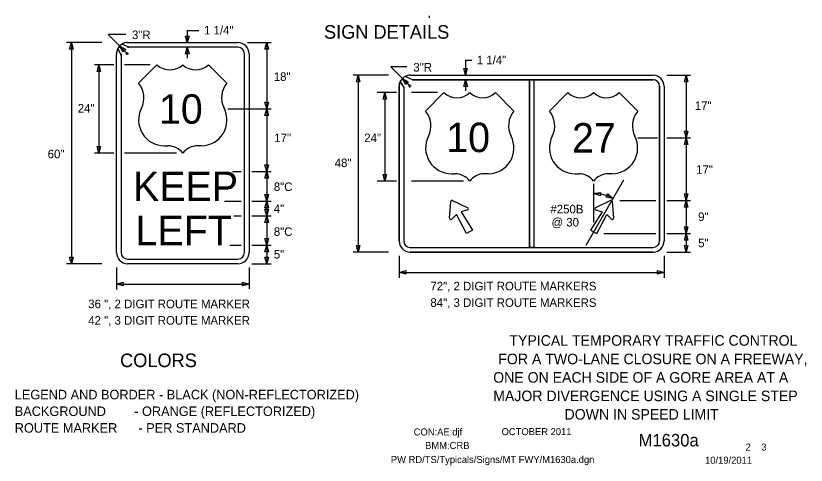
# Model space of a CAD drawing. Extents: x 16512 to 19512, y 5761 to 6974.
# Drawn here: x 17768 to 18466, y 5932 to 6328 of the extents above; entities that cross this region are included whole.
import ezdxf

# ---------------------------------------------------------------- set-up
doc = ezdxf.new("R2010")
doc.units = 0
for name, color, linetype in [('ALI_LEGAL_EX', 7, 'Continuous'), ('BORDER', 7, 'Continuous'), ('BORDER_SIGNAL_WO', 7, 'Continuous'), ('TRAFFIC_SIGNS_PR', 7, 'Continuous'), ('TYPICAL_EX', 7, 'Continuous'), ('TYPICAL_TEXT_DIMEN_PR', 7, 'Continuous')]:
    doc.layers.add(name, color=color, linetype=linetype)

msp = doc.modelspace()

# ---------------------------------------------------------------- linework, layer by layer
at = {"layer": 'ALI_LEGAL_EX'}
msp.add_lwpolyline([(18133.42, 6328.26), (18133.42, 6326.51)], dxfattribs=at)
at = {"layer": 'TRAFFIC_SIGNS_PR'}
for p, q in [((17859.5, 6300.96), (17858.5, 6299.45)), ((17868.29, 6300.52), (17862.19, 6303.27)), ((17867.09, 6304.58), (17964.59, 6304.58)), ((17857.34, 6119.33), (17857.34, 6294.83)), ((17858.53, 6299.39), (17861.4, 6293.35)), ((17861.4, 6294.83), (17861.4, 6119.33)), ((17964.59, 6300.52), (17867.09, 6300.52)), ((17970.27, 6119.33), (17970.27, 6294.83)), ((17974.34, 6294.83), (17974.34, 6119.33)), ((18118.56, 6271.83), (18112.33, 6274.85)), ((18116.61, 6275.88), (18331.11, 6275.88)), ((18116.61, 6275.88), (18331.11, 6275.88)), ((18106.86, 6266.13), (18106.86, 6129.63)), ((18106.86, 6129.63), (18106.86, 6266.13)), ((18107.78, 6270.14), (18110.91, 6265.1)), ((18118.55, 6271.82), (18221.83, 6271.82)), ((18331.11, 6271.82), (18118.55, 6271.82)), ((18221.83, 6271.82), (18221.83, 6123.95)), ((18225.89, 6271.82), (18225.89, 6123.95)), ((18225.89, 6271.82), (18331.11, 6271.82)), ((18336.8, 6266.13), (18336.8, 6220.38)), ((18336.8, 6129.63), (18336.8, 6266.13)), ((18340.86, 6266.13), (18340.86, 6129.63)), ((18340.86, 6266.13), (18340.86, 6129.63)), ((18110.92, 6265.08), (18110.92, 6129.63)), ((18110.92, 6265.08), (18110.92, 6129.63)), ((18336.8, 6220.38), (18336.8, 6129.63)), ((18151.46, 6149.74), (18152.61, 6164.46)), ((18154.12, 6165.33), (18167.44, 6158.97)), ((18293.59, 6165.33), (18280.28, 6158.97)), ((18296.26, 6149.74), (18295.1, 6164.46)), ((18116.61, 6123.95), (18331.11, 6123.95)), ((18116.61, 6119.88), (18331.11, 6119.88)), ((18331.11, 6119.88), (18116.61, 6119.88)), ((17867.09, 6113.64), (17964.59, 6113.64)), ((17964.59, 6109.58), (17867.09, 6109.58))]:
    msp.add_line(p, q, dxfattribs=at)
for points in [[(18118.55, 6271.82), (18118.53, 6271.83)], [(18110.91, 6265.1), (18110.92, 6265.08)], [(18167.28, 6157), (18161.55, 6155.42), (18171.77, 6139.25), (18166.37, 6136.13), (18157.48, 6153.07), (18153.25, 6148.9)], [(18280.44, 6157), (18286.16, 6155.42), (18275.95, 6139.25), (18281.34, 6136.13), (18290.24, 6153.07), (18294.46, 6148.9)]]:
    msp.add_lwpolyline(points, dxfattribs=at)
msp.add_lwpolyline([(18221.83, 6271.82), (18225.89, 6271.82), (18225.89, 6123.95), (18221.83, 6123.95)], close=True, dxfattribs=at)
for centre, radius, start, end in [((17867.09, 6294.83), 9.75, 90, 180), ((17866.5, 6297.01), 7.6, 85.58319, 124.53531), ((17964.59, 6294.83), 9.75, 0, 90), ((17864.37, 6295.43), 7.06, 145.86811, 184.82317), ((17855.94, 6294.09), 5.51, 352.24294, 7.75653), ((17867.69, 6304.95), 4.47, 262.2432, 277.7568), ((17964.59, 6294.83), 5.69, 0, 90), ((18116.61, 6266.13), 9.75, 90, 180), ((18116.61, 6266.13), 9.75, 90, 180), ((18115.93, 6269.32), 6.6, 84.11162, 123.06374), ((18331.11, 6266.13), 9.75, 0, 90), ((18331.11, 6266.13), 9.75, 0, 90), ((18112.99, 6266.84), 6.17, 147.60925, 186.56283), ((18117.55, 6279), 7.24, 277.81035, 278.05403), ((18331.11, 6266.13), 5.69, 0, 89.99421), ((18331.11, 6266.13), 5.69, 0, 90), ((18153.67, 6164.37), 1.06, 64.48226, 175.51774), ((18294.05, 6164.37), 1.06, 4.48226, 115.51774), ((18166.98, 6158.02), 1.06, 285.9885, 64.48226), ((18280.73, 6158.02), 1.06, 115.51774, 254.0115), ((18152.52, 6149.66), 1.06, 175.51775, 314.01151), ((18295.2, 6149.66), 1.06, 225.98849, 4.48225), ((18116.61, 6129.63), 9.75, 180, 270), ((18116.61, 6129.63), 9.75, 180, 270), ((18116.61, 6129.63), 5.69, 180, 270), ((18116.61, 6129.63), 5.69, 180, 270), ((18331.11, 6129.63), 9.75, 270, 0), ((18331.11, 6129.63), 5.69, 270, 0), ((18331.11, 6129.63), 9.75, 270, 0), ((18331.11, 6129.63), 5.69, 270, 0), ((17867.09, 6119.33), 9.75, 180, 270), ((17867.09, 6119.33), 5.69, 180, 270), ((17964.59, 6119.33), 5.69, 270, 0), ((17964.59, 6119.33), 9.75, 270, 0)]:
    msp.add_arc(centre, radius, start, end, dxfattribs=at)
at = {"layer": 'TYPICAL_EX'}
for p, q in [((17876.84, 6268.84), (17893.09, 6285.09)), ((17954.84, 6268.84), (17938.59, 6285.09)), ((18130.22, 6244.22), (18146.47, 6260.47)), ((18208.22, 6244.22), (18191.97, 6260.47)), ((18239.5, 6244.22), (18255.75, 6260.47)), ((18317.5, 6244.22), (18301.25, 6260.47)), ((17899.56, 6213.54), (17902.81, 6213.54)), ((17932.11, 6213.54), (17928.86, 6213.54)), ((18152.95, 6188.93), (18156.2, 6188.93)), ((18185.49, 6188.93), (18182.24, 6188.93)), ((18262.22, 6188.93), (18265.47, 6188.93)), ((18294.77, 6188.93), (18291.52, 6188.93))]:
    msp.add_line(p, q, dxfattribs=at)
for centre, radius, start, end in [((17904.46, 6296.92), 16.42, 226.14041, 313.85958), ((17927.21, 6296.92), 16.42, 226.14042, 313.85959), ((17861.44, 6255.82), 20.16, 333.09768, 40.19361), ((17970.24, 6255.82), 20.16, 139.80639, 206.90233), ((18157.85, 6272.31), 16.42, 226.14041, 313.85958), ((18180.59, 6272.31), 16.42, 226.14042, 313.85959), ((18267.12, 6272.31), 16.42, 226.14041, 313.85958), ((18289.87, 6272.31), 16.42, 226.14042, 313.85959), ((17899.6, 6236.27), 22.73, 152.6698, 269.90132), ((17932.07, 6236.27), 22.73, 270.09868, 27.3302), ((18114.82, 6231.21), 20.16, 333.09768, 40.19361), ((18223.62, 6231.21), 20.16, 139.80639, 206.90233), ((18224.1, 6231.21), 20.16, 333.09768, 40.19361), ((18332.9, 6231.21), 20.16, 139.80639, 206.90233), ((18152.99, 6211.66), 22.73, 152.6698, 269.90132), ((18185.45, 6211.66), 22.73, 270.09868, 27.3302), ((18262.27, 6211.66), 22.73, 152.6698, 269.90132), ((18294.73, 6211.66), 22.73, 270.09868, 27.3302), ((17902.85, 6197.26), 16.28, 37.1038, 90.13853), ((17928.82, 6197.26), 16.28, 89.86147, 142.8962), ((18156.24, 6172.65), 16.28, 37.1038, 90.13853), ((18182.2, 6172.65), 16.28, 89.86147, 142.8962), ((18265.52, 6172.65), 16.28, 37.1038, 90.13853), ((18291.48, 6172.65), 16.28, 89.86147, 142.8962)]:
    msp.add_arc(centre, radius, start, end, dxfattribs=at)
at = {"layer": 'TYPICAL_TEXT_DIMEN_PR'}
for p, q in [((17919.81, 6315.34), (17919.81, 6304.58)), ((17919.81, 6315.34), (17929.91, 6315.34)), ((17865.71, 6311.86), (17850.05, 6311.86)), ((17850.05, 6311.86), (17860.29, 6301.63)), ((17919.81, 6304.58), (17918.24, 6310.44)), ((17918.24, 6310.44), (17919.81, 6310.44)), ((17919.81, 6310.44), (17921.38, 6310.44)), ((17921.38, 6310.44), (17919.81, 6304.58)), ((17844.51, 6304.58), (17813.21, 6304.58)), ((17815.98, 6298.72), (17817.55, 6304.58)), ((17817.55, 6304.58), (17817.55, 6109.58)), ((17817.55, 6304.58), (17819.12, 6298.72)), ((17860.29, 6301.63), (17866.85, 6295.07)), ((17863.32, 6296.37), (17860.29, 6301.63)), ((17860.29, 6301.63), (17865.54, 6298.6)), ((17972.88, 6304.58), (17993.84, 6304.58)), ((17988.37, 6298.72), (17989.94, 6304.58)), ((17989.94, 6304.58), (17989.94, 6246.08)), ((17989.94, 6304.58), (17991.51, 6298.72)), ((17817.55, 6298.72), (17815.98, 6298.72)), ((17819.12, 6298.72), (17817.55, 6298.72)), ((17864.43, 6297.49), (17863.32, 6296.37)), ((17865.54, 6298.6), (17864.43, 6297.49)), ((17865.64, 6295.07), (17868.05, 6295.07)), ((17866.85, 6293.86), (17866.85, 6296.28)), ((17918.28, 6294.66), (17919.86, 6300.52)), ((17919.86, 6294.66), (17918.28, 6294.66)), ((17919.86, 6300.52), (17919.86, 6290.77)), ((17919.86, 6300.52), (17921.43, 6294.66)), ((17921.43, 6294.66), (17919.86, 6294.66)), ((17989.94, 6298.72), (17988.37, 6298.72)), ((17991.51, 6298.72), (17989.94, 6298.72)), ((18165.47, 6289.03), (18165.47, 6275.88)), ((18165.47, 6289.03), (18170.99, 6289.03)), ((17854.96, 6285.08), (17837.84, 6285.08)), ((17840.16, 6279.22), (17841.73, 6285.08)), ((17841.73, 6285.08), (17841.73, 6207.08)), ((17841.73, 6285.08), (17843.3, 6279.22)), ((17887.2, 6285.08), (17864.33, 6285.08)), ((18113.75, 6283.17), (18099.57, 6283.17)), ((18099.57, 6283.17), (18109.72, 6273.02)), ((18165.47, 6275.88), (18163.89, 6281.74)), ((18163.89, 6281.74), (18165.47, 6281.74)), ((18165.47, 6281.74), (18167.04, 6281.74)), ((18167.04, 6281.74), (18165.47, 6275.88)), ((17841.73, 6279.22), (17840.16, 6279.22)), ((17843.3, 6279.22), (17841.73, 6279.22)), ((18097.62, 6275.88), (18066.33, 6275.88)), ((18069.1, 6270.02), (18070.67, 6275.88)), ((18070.67, 6275.88), (18070.67, 6119.88)), ((18070.67, 6275.88), (18072.24, 6270.02)), ((18109.72, 6273.02), (18116.37, 6266.37)), ((18112.76, 6267.76), (18109.72, 6273.02)), ((18109.72, 6273.02), (18114.98, 6269.99)), ((18343.23, 6275.88), (18364.19, 6275.88)), ((18358.72, 6270.02), (18360.29, 6275.88)), ((18360.29, 6275.88), (18360.29, 6220.63)), ((18360.29, 6275.88), (18361.86, 6270.02)), ((18070.67, 6270.02), (18069.1, 6270.02)), ((18072.24, 6270.02), (18070.67, 6270.02)), ((18113.87, 6268.88), (18112.76, 6267.76)), ((18114.98, 6269.99), (18113.87, 6268.88)), ((18115.16, 6266.37), (18117.58, 6266.37)), ((18116.37, 6265.16), (18116.37, 6267.58)), ((18163.94, 6265.96), (18165.51, 6271.82)), ((18163.94, 6265.96), (18165.51, 6271.82)), ((18165.51, 6271.82), (18165.51, 6262.07)), ((18165.51, 6271.82), (18167.08, 6265.96)), ((18165.51, 6271.82), (18167.08, 6265.96)), ((18360.29, 6270.02), (18358.72, 6270.02)), ((18361.86, 6270.02), (18360.29, 6270.02)), ((18104.49, 6260.47), (18087.36, 6260.47)), ((18092.65, 6254.61), (18094.23, 6260.47)), ((18094.23, 6260.47), (18094.23, 6182.47)), ((18094.23, 6260.47), (18095.8, 6254.61)), ((18140.59, 6260.47), (18117.71, 6260.47)), ((18165.51, 6265.96), (18163.94, 6265.96)), ((18165.51, 6265.96), (18163.94, 6265.96)), ((18167.08, 6265.96), (18165.51, 6265.96)), ((18167.08, 6265.96), (18165.51, 6265.96)), ((18094.23, 6254.61), (18092.65, 6254.61)), ((18095.8, 6254.61), (18094.23, 6254.61)), ((17955.73, 6246.08), (17993.84, 6246.08)), ((17989.94, 6246.08), (17988.37, 6251.94)), ((17988.37, 6251.94), (17989.94, 6251.94)), ((17988.37, 6240.22), (17989.94, 6246.08)), ((17989.94, 6251.94), (17991.51, 6251.94)), ((17991.51, 6251.94), (17989.94, 6246.08)), ((17989.94, 6246.08), (17989.94, 6190.83)), ((17989.94, 6246.08), (17991.51, 6240.22)), ((17989.94, 6240.22), (17988.37, 6240.22)), ((17991.51, 6240.22), (17989.94, 6240.22)), ((18360.29, 6220.63), (18358.72, 6226.49)), ((18358.72, 6226.49), (18360.29, 6226.49)), ((18360.29, 6226.49), (18361.86, 6226.49)), ((18361.86, 6226.49), (18360.29, 6220.63)), ((18317.67, 6220.63), (18334.82, 6220.63)), ((18343.23, 6220.63), (18364.19, 6220.63)), ((18358.72, 6214.77), (18360.29, 6220.63)), ((18360.29, 6220.63), (18360.29, 6165.38)), ((18360.29, 6220.63), (18361.86, 6214.77)), ((17841.73, 6207.08), (17840.16, 6212.94)), ((17840.16, 6212.94), (17841.73, 6212.94)), ((17841.73, 6212.94), (17843.3, 6212.94)), ((17843.3, 6212.94), (17841.73, 6207.08)), ((18360.29, 6214.77), (18358.72, 6214.77)), ((18361.86, 6214.77), (18360.29, 6214.77)), ((17854.96, 6207.08), (17837.84, 6207.08)), ((17910.33, 6207.08), (17864.33, 6207.08)), ((17989.94, 6190.83), (17988.37, 6196.69)), ((17988.37, 6196.69), (17989.94, 6196.69)), ((17989.94, 6196.69), (17991.51, 6196.69)), ((17991.51, 6196.69), (17989.94, 6190.83)), ((17959.66, 6190.83), (17967.35, 6190.83)), ((17976.71, 6190.83), (17993.84, 6190.83)), ((17988.37, 6184.97), (17989.94, 6190.83)), ((17989.94, 6190.83), (17989.94, 6164.83)), ((17989.94, 6190.83), (17991.51, 6184.97)), ((17989.94, 6184.97), (17988.37, 6184.97)), ((17991.51, 6184.97), (17989.94, 6184.97)), ((18104.49, 6182.47), (18087.36, 6182.47)), ((18094.23, 6182.47), (18092.65, 6188.33)), ((18092.65, 6188.33), (18094.23, 6188.33)), ((18094.23, 6188.33), (18095.8, 6188.33)), ((18095.8, 6188.33), (18094.23, 6182.47)), ((18163.71, 6182.47), (18117.71, 6182.47)), ((18271.89, 6125.98), (18305.13, 6183.57)), ((18278.65, 6146.14), (18278.65, 6180.13)), ((17989.94, 6164.83), (17988.37, 6170.69)), ((17988.37, 6170.69), (17989.94, 6170.69)), ((17989.94, 6170.69), (17991.51, 6170.69)), ((17991.51, 6170.69), (17989.94, 6164.83)), ((18278.67, 6171.58), (18284.67, 6172.54)), ((18284.35, 6169.41), (18278.67, 6171.58)), ((18284.51, 6170.97), (18284.35, 6169.41)), ((18284.67, 6172.54), (18284.51, 6170.97)), ((18289.66, 6168.25), (18290.34, 6169.67)), ((18290.34, 6169.67), (18291.03, 6171.08)), ((18291.03, 6171.08), (18295.62, 6167.12)), ((18360.29, 6165.38), (18358.72, 6171.24)), ((18358.72, 6171.24), (18360.29, 6171.24)), ((18360.29, 6171.24), (18361.86, 6171.24)), ((18361.86, 6171.24), (18360.29, 6165.38)), ((17952.65, 6164.83), (17967.35, 6164.83)), ((17976.71, 6164.83), (17993.84, 6164.83)), ((17988.37, 6158.97), (17989.94, 6164.83)), ((17989.94, 6164.83), (17989.94, 6151.83)), ((17989.94, 6164.83), (17991.51, 6158.97)), ((18295.62, 6167.12), (18289.66, 6168.25)), ((18301.6, 6165.38), (18333.47, 6165.38)), ((18343.23, 6165.38), (18364.19, 6165.38)), ((18358.72, 6159.52), (18360.29, 6165.38)), ((18360.29, 6165.38), (18360.29, 6136.13)), ((18360.29, 6165.38), (18361.86, 6159.52)), ((17989.94, 6158.97), (17988.37, 6158.97)), ((17989.94, 6151.83), (17988.37, 6157.69)), ((17988.37, 6157.69), (17989.94, 6157.69)), ((17991.51, 6158.97), (17989.94, 6158.97)), ((17989.94, 6157.69), (17991.51, 6157.69)), ((17991.51, 6157.69), (17989.94, 6151.83)), ((18360.29, 6159.52), (18358.72, 6159.52)), ((18361.86, 6159.52), (18360.29, 6159.52)), ((17961, 6151.83), (17967.35, 6151.83)), ((17976.71, 6151.83), (17993.84, 6151.83)), ((17988.37, 6145.97), (17989.94, 6151.83)), ((17989.94, 6151.83), (17989.94, 6125.83)), ((17989.94, 6151.83), (17991.51, 6145.97)), ((17989.94, 6145.97), (17988.37, 6145.97)), ((17991.51, 6145.97), (17989.94, 6145.97)), ((18360.29, 6136.13), (18358.72, 6141.99)), ((18358.72, 6141.99), (18360.29, 6141.99)), ((18360.29, 6141.99), (18361.86, 6141.99)), ((18361.86, 6141.99), (18360.29, 6136.13)), ((18287.46, 6136.13), (18333.47, 6136.13)), ((18343.23, 6136.13), (18364.19, 6136.13)), ((18358.72, 6130.27), (18360.29, 6136.13)), ((18360.29, 6136.13), (18360.29, 6119.88)), ((18360.29, 6136.13), (18361.86, 6130.27)), ((17989.94, 6125.83), (17988.37, 6131.69)), ((17988.37, 6131.69), (17989.94, 6131.69)), ((17989.94, 6131.69), (17991.51, 6131.69)), ((17991.51, 6131.69), (17989.94, 6125.83)), ((18360.29, 6130.27), (18358.72, 6130.27)), ((18361.86, 6130.27), (18360.29, 6130.27)), ((17957.5, 6125.83), (17967.35, 6125.83)), ((17976.71, 6125.83), (17993.84, 6125.83)), ((17988.37, 6119.97), (17989.94, 6125.83)), ((17989.94, 6119.97), (17988.37, 6119.97)), ((17989.94, 6125.83), (17989.94, 6109.58)), ((17989.94, 6125.83), (17991.51, 6119.97)), ((17991.51, 6119.97), (17989.94, 6119.97)), ((18097.62, 6119.88), (18066.33, 6119.88)), ((18070.67, 6119.88), (18069.1, 6125.74)), ((18069.1, 6125.74), (18070.67, 6125.74)), ((18070.67, 6125.74), (18072.24, 6125.74)), ((18072.24, 6125.74), (18070.67, 6119.88)), ((18343.23, 6119.88), (18360.36, 6119.88)), ((18343.23, 6119.88), (18364.19, 6119.88)), ((18343.23, 6119.88), (18360.36, 6119.88)), ((18360.29, 6119.88), (18358.72, 6125.74)), ((18358.72, 6125.74), (18360.29, 6125.74)), ((18360.29, 6125.74), (18361.86, 6125.74)), ((18361.86, 6125.74), (18360.29, 6119.88)), ((17817.55, 6109.58), (17815.98, 6115.44)), ((17815.98, 6115.44), (17817.55, 6115.44)), ((17817.55, 6115.44), (17819.12, 6115.44)), ((17819.12, 6115.44), (17817.55, 6109.58)), ((17989.94, 6109.58), (17988.37, 6115.44)), ((17988.37, 6115.44), (17989.94, 6115.44)), ((17989.94, 6115.44), (17991.51, 6115.44)), ((17991.51, 6115.44), (17989.94, 6109.58)), ((18106.86, 6116.54), (18106.86, 6096.98)), ((18340.86, 6116.54), (18340.86, 6096.98)), ((17844.51, 6109.58), (17813.21, 6109.58)), ((17857.34, 6106.24), (17857.34, 6086.89)), ((17974.34, 6106.24), (17974.34, 6087.34)), ((17976.71, 6109.58), (17993.84, 6109.58)), ((18106.86, 6101.91), (18112.72, 6103.48)), ((18106.86, 6101.91), (18340.86, 6101.91)), ((18112.72, 6100.34), (18106.86, 6101.91)), ((18112.72, 6103.48), (18112.72, 6101.91)), ((18112.72, 6101.91), (18112.72, 6100.34)), ((18335, 6101.91), (18335, 6103.48)), ((18335, 6103.48), (18340.86, 6101.91)), ((18340.86, 6101.91), (18335, 6100.34)), ((18335, 6100.34), (18335, 6101.91)), ((17857.34, 6091.61), (17863.2, 6093.18)), ((17857.34, 6091.61), (17974.34, 6091.61)), ((17863.2, 6090.04), (17857.34, 6091.61)), ((17863.2, 6093.18), (17863.2, 6091.61)), ((17863.2, 6091.61), (17863.2, 6090.04)), ((17968.47, 6091.61), (17968.47, 6093.18)), ((17968.47, 6093.18), (17974.34, 6091.61)), ((17974.34, 6091.61), (17968.47, 6090.04)), ((17968.47, 6090.04), (17968.47, 6091.61))]:
    msp.add_line(p, q, dxfattribs=at)
msp.add_arc((18278.84, 6137.14), 34.39, 60.74521, 90.32117, dxfattribs=at)

# ---------------------------------------------------------------- texts
at = {"layer": 'BORDER'}
for s, p in [('TYPICAL TEMPORARY TRAFFIC CONTROL', (18204.21, 6037.21)), ('FOR A TWO-LANE CLOSURE ON A FREEWAY,', (18194.41, 6020.91)), ('ONE ON EACH SIDE OF A GORE AREA AT A ', (18189.92, 6004.62)), ('MAJOR DIVERGENCE USING A SINGLE STEP ', (18189.92, 5988.32)), ('DOWN IN SPEED LIMIT', (18252.92, 5972.02))]:
    msp.add_text(s, height=9.3, dxfattribs=at).set_placement(p)
at = {"layer": 'BORDER_SIGNAL_WO'}
for s, height, p in [('CON:AE:djf  ', 6.2, (18119.69, 5958.06)), ('    OCTOBER 2011    ', 6.2, (18188.08, 5958.34)), ('    M1630a   ', 11, (18301.86, 5948.38)), ('BMM:CRB   ', 6.2, (18129.81, 5946.17)), (' 2    3 ', 6.2, (18410.45, 5944.7)), ('PW RD/TS/Typicals/Signs/MT FWY/M1630a.dgn      ', 6.2, (18099.55, 5933.71)), ('10/19/2011    ', 6.2, (18376.93, 5933.13))]:
    msp.add_text(s, height=height, dxfattribs=at).set_placement(p)
at = {"layer": 'TRAFFIC_SIGNS_PR'}
for s, p in [('10', (17894.81, 6233.08)), ('10', (18148.46, 6208.01)), ('27', (18259.47, 6207.65)), ('KEEP', (17871.94, 6164.83)), ('LEFT', (17874.17, 6125.83))]:
    msp.add_text(s, height=26, dxfattribs=at).set_placement(p)
at = {"layer": 'TYPICAL_TEXT_DIMEN_PR'}
for s, height, p in [('3"R', 7.55, (17870.98, 6307.74)), ('1 1/4"', 7.55, (17934.61, 6311.84)), ('SIGN DETAILS', 12, (18040.56, 6308.05)), ('1 1/4"', 7.55, (18175.39, 6285.46)), ('3"R', 7.55, (18119.39, 6279.09)), ('18"', 7.55, (17996.18, 6270.85)), ('17"', 7.55, (18367.87, 6245.24)), ('24"', 7.55, (17823.18, 6242.97)), ('17"', 7.55, (17996.64, 6216.81)), ('24"', 7.55, (18076.08, 6216.8)), ('60"', 7.55, (17796.58, 6202.6)), ('48"', 7.55, (18049.97, 6194.78)), ('17"', 7.55, (18369.07, 6188.89)), ('8"C', 7.55, (17996.21, 6173.69)), ('4" ', 7.55, (17996.21, 6154.43)), ('#250B', 7.55, (18240.42, 6153.98)), ('9"', 7.55, (18370.85, 6147.23)), ('@ 30', 7.55, (18241.36, 6142.43)), ('8"C', 7.55, (17996.21, 6134.1)), ('5"', 7.55, (18370.85, 6124.13)), ('5" ', 7.55, (17996.21, 6114.13)), ('72", 2 DIGIT ROUTE MARKERS', 7.55, (18134.44, 6086.05)), ('36 ", 2 DIGIT ROUTE MARKER', 7.55, (17832.38, 6070.35)), ('84", 3 DIGIT ROUTE MARKERS', 7.55, (18134.44, 6071.5)), ('42 ", 3 DIGIT ROUTE MARKER', 7.55, (17832.38, 6055.8)), ('COLORS', 12, (17860.53, 6018.33)), ('LEGEND AND BORDER - BLACK (NON-REFLECTORIZED)', 8.4, (17767.53, 5989.92)), ('BACKGROUND        - ORANGE (REFLECTORIZED)', 8.4, (17767.53, 5975.22)), ('ROUTE MARKER      - PER STANDARD', 8.4, (17767.53, 5960.52))]:
    msp.add_text(s, height=height, dxfattribs=at).set_placement(p)

doc.saveas('drawing.dxf')
